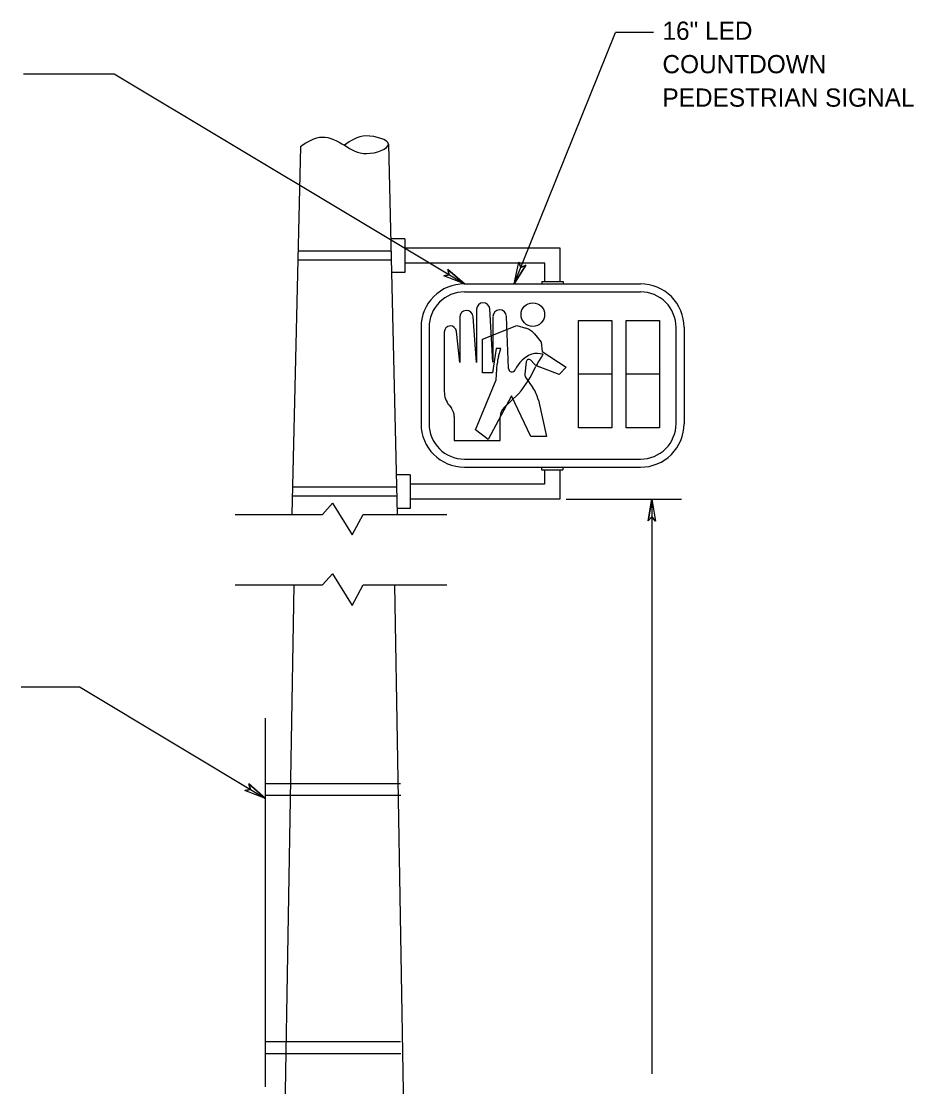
# Model space of a CAD drawing. Extents: x 12.4 to 21.9, y 5.3 to 15.4.
# Drawn here: x 16.297 to 19.233, y 11.889 to 15.394 of the extents above; entities that cross this region are included whole.
import ezdxf

# ---------------------------------------------------------------- set-up
doc = ezdxf.new("R2010")
doc.units = 0
for name, color, linetype in [('DETL-DIMS', 7, 'Continuous'), ('DETL-LINE', 7, 'Continuous'), ('DETL-NOTE', 7, 'Continuous')]:
    doc.layers.add(name, color=color, linetype=linetype)

msp = doc.modelspace()

# ---------------------------------------------------------------- linework, layer by layer
at = {"layer": 'DETL-DIMS'}
for p, q in [((17.9183, 14.5303), (18.2512, 15.3573)), ((18.3767, 15.3573), (18.2512, 15.3573)), ((16.3037, 15.2209), (16.6022, 15.2209)), ((16.6022, 15.2209), (17.7546, 14.5304)), ((17.9183, 14.5303), (17.9331, 14.6014)), ((17.9183, 14.5303), (17.9564, 14.5919)), ((17.9398, 14.5842), (17.9331, 14.6014)), ((17.9564, 14.5919), (17.9398, 14.5842)), ((17.7048, 14.5602), (17.6867, 14.5563)), ((17.7546, 14.5304), (17.6867, 14.5563)), ((17.7546, 14.5304), (17.6998, 14.5779)), ((17.6998, 14.5779), (17.7048, 14.5602)), ((18.0888, 13.8217), (18.4691, 13.8217)), ((18.3716, 13.8217), (18.3586, 13.7503)), ((18.3716, 13.8217), (18.3838, 13.7501)), ((18.3716, 13.8217), (18.3716, 11.932)), ((18.3586, 13.7503), (18.3713, 13.7637)), ((18.3713, 13.7637), (18.3838, 13.7501)), ((16.4902, 13.2038), (16.2965, 13.2038)), ((16.4902, 13.2038), (17.1001, 12.8374)), ((17.0505, 12.8675), (17.0324, 12.8638)), ((17.1001, 12.8374), (17.0324, 12.8638)), ((17.1001, 12.8374), (17.0456, 12.8853)), ((17.0456, 12.8853), (17.0505, 12.8675))]:
    msp.add_line(p, q, dxfattribs=at)
for points in [[(17.9564, 14.5919), (17.9183, 14.5303), (17.9331, 14.6014), (17.9398, 14.5842)], [(17.6998, 14.5779), (17.7546, 14.5304), (17.6867, 14.5563), (17.7048, 14.5602)], [(18.3586, 13.7503), (18.3716, 13.8217), (18.3838, 13.7501), (18.3713, 13.7637)], [(17.0456, 12.8853), (17.1001, 12.8374), (17.0324, 12.8638), (17.0505, 12.8675)]]:
    msp.add_lwpolyline(points, close=True, dxfattribs=at)
for points in [[(17.0004, 13.7722), (17.2871, 13.7722), (17.3209, 13.809), (17.3856, 13.7045), (17.4215, 13.7722), (17.6962, 13.7722)], [(17.0004, 13.5402), (17.2871, 13.5402), (17.3209, 13.577), (17.3856, 13.4725), (17.4215, 13.5402), (17.6962, 13.5402)]]:
    msp.add_lwpolyline(points, dxfattribs=at)
at = {"layer": 'DETL-LINE'}
for p, q in [((17.215, 14.9828), (17.1869, 13.7722)), ((17.5048, 14.9896), (17.5331, 13.7722)), ((17.5582, 14.6783), (17.512, 14.6783)), ((17.5582, 14.6783), (17.5582, 14.5683)), ((17.5129, 14.6383), (17.2063, 14.6383)), ((18.0695, 14.6483), (17.5582, 14.6483)), ((18.0695, 14.5387), (18.0695, 14.6483)), ((17.5136, 14.6083), (17.2063, 14.6083)), ((18.0195, 14.5983), (17.5582, 14.5983)), ((18.0195, 14.5387), (18.0195, 14.5983)), ((17.5582, 14.5683), (17.5146, 14.5683)), ((17.7546, 14.5303), (18.3343, 14.5304)), ((18.0095, 14.5387), (18.0795, 14.5387)), ((18.0095, 14.5387), (18.0095, 14.5303)), ((18.0795, 14.5387), (18.0795, 14.5303)), ((17.7546, 14.5037), (18.3343, 14.5038)), ((17.7945, 14.4466), (17.7945, 14.2714)), ((17.8483, 14.2733), (17.8381, 14.4479)), ((17.7392, 14.4203), (17.7392, 14.2713)), ((17.7945, 14.2714), (17.7833, 14.4219)), ((17.8483, 14.4224), (17.8483, 14.2733)), ((17.8996, 14.2521), (17.8931, 14.4233)), ((18.13, 14.057), (18.1301, 14.41)), ((18.1301, 14.41), (18.2395, 14.41)), ((18.2395, 14.41), (18.2394, 14.057)), ((18.2868, 14.41), (18.3963, 14.41)), ((18.2868, 14.057), (18.2868, 14.41)), ((18.3963, 14.41), (18.3961, 14.057)), ((17.6118, 14.3874), (17.6118, 14.0702)), ((17.6383, 14.3874), (17.6383, 14.0702)), ((17.6884, 14.372), (17.6883, 14.1759)), ((17.7392, 14.2713), (17.7283, 14.3741)), ((17.8135, 14.3488), (17.9273, 14.3933)), ((17.9273, 14.3933), (17.9571, 14.3843)), ((18.4507, 14.3874), (18.4507, 14.0702)), ((18.4773, 14.3874), (18.4773, 14.0702)), ((17.8135, 14.2375), (17.8135, 14.3488)), ((17.9847, 14.3662), (18.0076, 14.3391)), ((18.0076, 14.3391), (18.0107, 14.3081)), ((17.8591, 14.3172), (17.8464, 14.2375)), ((17.8744, 14.3172), (17.8591, 14.3172)), ((17.8668, 14.2913), (17.8744, 14.3172)), ((18.0107, 14.3081), (18.0891, 14.2564)), ((17.8586, 14.2144), (17.8624, 14.2669)), ((17.9579, 14.2741), (17.9529, 14.2338)), ((17.9844, 14.2672), (17.9728, 14.279)), ((17.8464, 14.2375), (17.8135, 14.2375)), ((18.0666, 14.232), (18.0001, 14.2571)), ((18.0891, 14.2564), (18.0666, 14.232)), ((18.2394, 14.2335), (18.1301, 14.2335)), ((18.3962, 14.2335), (18.2869, 14.2335)), ((17.791, 14.0506), (17.8586, 14.2144)), ((17.9554, 14.2237), (17.9798, 14.1887)), ((17.9097, 14.1625), (17.833, 14.0183)), ((17.8858, 14.1241), (17.9328, 14.1683)), ((17.9735, 14.0281), (17.9097, 14.1625)), ((17.7041, 14.1308), (17.7116, 14.1214)), ((17.998, 14.1475), (18.0246, 14.0281)), ((17.7211, 14.0942), (17.7211, 14.0156)), ((17.872, 14.0156), (17.872, 14.0923)), ((18.2394, 14.057), (18.13, 14.057)), ((18.3961, 14.057), (18.2868, 14.057)), ((17.833, 14.0183), (17.791, 14.0506)), ((18.0246, 14.0281), (17.9735, 14.0281)), ((17.7211, 14.0156), (17.872, 14.0156)), ((17.7546, 13.9538), (18.3343, 13.9538)), ((17.7546, 13.9273), (18.3343, 13.9272)), ((18.008, 13.9273), (18.008, 13.9189)), ((18.008, 13.9189), (18.078, 13.9189)), ((18.018, 13.9189), (18.018, 13.8717)), ((18.068, 13.9189), (18.068, 13.8217)), ((18.078, 13.9273), (18.078, 13.9189)), ((17.5756, 13.9017), (17.5301, 13.9017)), ((17.5756, 13.9017), (17.5756, 13.7917)), ((17.531, 13.8617), (17.1892, 13.8617)), ((18.018, 13.8717), (17.5756, 13.8717)), ((17.5317, 13.8317), (17.1892, 13.8317)), ((18.068, 13.8217), (17.5756, 13.8217)), ((17.5756, 13.7917), (17.5326, 13.7917)), ((17.1109, 8.6403), (17.1939, 13.5402)), ((17.609, 8.6403), (17.526, 13.5402)), ((17.1001, 11.8893), (17.1001, 13.1019)), ((17.1001, 12.8871), (17.5446, 12.8871)), ((17.1001, 12.8483), (17.5452, 12.8483)), ((17.1001, 12.0376), (17.5446, 12.0376)), ((17.1001, 11.9989), (17.5452, 11.9989))]:
    msp.add_line(p, q, dxfattribs=at)
msp.add_circle((17.9796, 14.4293), 0.0388, dxfattribs=at)
for centre, radius, start, end in [((17.7546, 14.3875), 0.1429, 90, 180.0005), ((18.3344, 14.3874), 0.1429, 359.9976, 90.0088), ((17.7546, 14.3875), 0.1164, 90, 180.0005), ((18.3344, 14.3874), 0.1164, 359.9976, 90.0088), ((17.7612, 14.4204), 0.0221, 4.2401, 180.0004), ((17.8163, 14.4467), 0.0218, 3.3417, 179.9989), ((17.8706, 14.4225), 0.0224, 2.1708, 180.0016), ((17.7083, 14.372), 0.0201, 5.998, 180), ((17.9402, 14.3287), 0.0582, 40.297, 73.1627), ((17.9938, 14.2303), 0.0711, 74.3494, 104.0253), ((17.9784, 14.2586), 0.1164, 163.6157, 175.8748), ((18.012, 14.2067), 0.0992, 110.9547, 155.5375), ((17.9665, 14.273), 0.00873, 44.539, 172.9798), ((18.0154, 14.298), 0.0436, 224.6023, 249.3752), ((18.4733, 14.0026), 0.5474, 147.2376, 152.1695), ((17.9111, 14.2526), 0.0116, 182.1702, 335.5375), ((17.612, 14.4327), 0.4156, 320.5012, 335.1658), ((17.9673, 14.2322), 0.0145, 172.9842, 214.9011), ((17.761, 14.1761), 0.0727, 179.9999, 218.4874), ((17.8844, 14.1222), 0.1164, 12.5686, 34.9017), ((17.6774, 14.0943), 0.0436, 0.001, 38.4866), ((17.9156, 14.0924), 0.0436, 133.2121, 180.001), ((17.7546, 14.0703), 0.1429, 180.0009, 270.0007), ((17.7546, 14.0703), 0.1164, 180.0009, 270.0007), ((18.3344, 14.0702), 0.1164, 269.9959, 359.9976), ((18.3344, 14.0702), 0.1429, 269.9959, 359.9976)]:
    msp.add_arc(centre, radius, start, end, dxfattribs=at)
msp.add_spline([(17.215, 14.9828), (17.2868, 15.0135), (17.3599, 14.9862), (17.433, 14.9589), (17.5048, 14.9896), (17.4317, 15.0169), (17.3599, 14.9862)], degree=3, dxfattribs=at)

# ---------------------------------------------------------------- texts
at = {"layer": 'DETL-NOTE'}
for s, p in [('16" LED', (18.4062, 15.3332)), ('COUNTDOWN', (18.4062, 15.2232)), ('PEDESTRIAN SIGNAL', (18.4062, 15.1132))]:
    msp.add_text(s, height=0.06, dxfattribs=at).set_placement(p)

doc.saveas('drawing.dxf')
